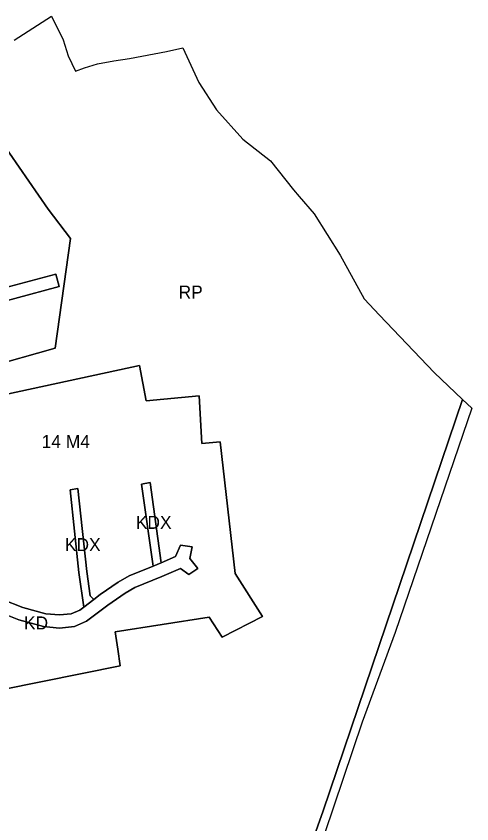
# Model space of a CAD drawing. Extents: x 7437831 to 7440315, y 5545798 to 5547888.
# Drawn here: x 7439964 to 7440315, y 5546851 to 5547473 of the extents above; entities that cross this region are included whole.
import ezdxf

# ---------------------------------------------------------------- set-up
doc = ezdxf.new("R2010")
doc.units = 0
doc.layers.add('linie_rozgraniczajace', color=7, linetype='Continuous')
doc.layers.add('oznaczenia_przeznaczen', color=7, linetype='Continuous')

msp = doc.modelspace()

# ---------------------------------------------------------------- linework, layer by layer
at = {"layer": 'linie_rozgraniczajace'}
for points in [[(7439963.01, 5547454.6), (7439991.67, 5547473.21), (7440000.6, 5547454.89), (7440004.46, 5547442.6), (7440010.06, 5547430.72), (7440017.22, 5547433.51), (7440027.12, 5547436.37), (7440039.57, 5547438.77), (7440051.74, 5547440.46), (7440080.33, 5547445.88), (7440092.89, 5547448.73), (7440105.07, 5547422.15), (7440118.61, 5547401.15), (7440138.87, 5547378.47), (7440160.22, 5547361.74), (7440178.05, 5547339.51), (7440182.37, 5547334.31), (7440194, 5547320.9), (7440214.02, 5547289.14), (7440232.3, 5547255.4), (7440244.18, 5547242.73), (7440286.26, 5547198.58), (7440308.05, 5547177.94), (7440200.75, 5546860.84), (7440127.28, 5546653.58)], [(7439941.63, 5547202.42), (7439994.44, 5547217.29), (7440006.23, 5547301.94), (7439989.21, 5547324.61), (7439951.69, 5547378.41)], [(7439951.69, 5547378.41), (7439989.21, 5547324.61), (7440006.23, 5547301.94), (7439994.44, 5547217.29), (7439941.63, 5547202.42)], [(7439929.04, 5547246.52), (7439997.61, 5547264.78), (7439995.02, 5547274.44), (7439925.61, 5547255.95)], [(7439925.61, 5547255.95), (7439995.02, 5547274.44), (7439997.61, 5547264.78), (7439929.04, 5547246.52)], [(7439892.92, 5546942.17), (7440044.56, 5546972.61), (7440042.79, 5546985.48), (7440040.74, 5546998.78), (7440113.06, 5547010.07), (7440123.08, 5546994.81), (7440154.06, 5547010.54), (7440133.02, 5547043.84), (7440121.64, 5547145.28), (7440107.55, 5547143.9), (7440105.31, 5547180.69), (7440064.52, 5547176.81), (7440059.38, 5547204.07), (7439948.78, 5547180.1)], [(7439948.78, 5547180.1), (7440059.38, 5547204.07), (7440064.52, 5547176.81), (7440105.31, 5547180.69), (7440107.55, 5547143.9), (7440121.64, 5547145.28), (7440133.02, 5547043.84), (7440154.06, 5547010.54), (7440123.08, 5546994.81), (7440113.06, 5547010.07), (7440040.74, 5546998.78), (7440042.79, 5546985.48), (7440044.56, 5546972.61), (7439892.92, 5546942.17)], [(7439936.88, 5547019.85), (7439966.48, 5547007.99), (7439985.57, 5547002.9), (7439997.86, 5547001.76), (7440009.46, 5547002.98), (7440018.66, 5547006.94), (7440035.1, 5547019.42), (7440048.31, 5547028.54), (7440055.98, 5547032.86), (7440076.73, 5547041.45), (7440091.03, 5547047.6), (7440097.55, 5547042.98), (7440104.36, 5547047.52), (7440098.28, 5547055.21), (7440099.9, 5547064.26), (7440090.96, 5547065.69), (7440087.08, 5547056.78), (7440076.17, 5547052.1), (7440067.66, 5547113.91), (7440060.9, 5547112.64), (7440069.89, 5547049.44), (7440051.59, 5547041.87), (7440043, 5547037.02), (7440029.23, 5547027.52), (7440024.35, 5547023.81), (7440021.4, 5547026.44), (7440018.79, 5547045.22), (7440012.09, 5547109.24), (7440006.18, 5547108.13), (7440012.84, 5547044.5), (7440016.52, 5547017.87), (7440013.59, 5547015.64), (7440006.91, 5547012.76), (7439997.8, 5547011.81), (7439987.33, 5547012.78), (7439969.62, 5547017.51), (7439953.87, 5547023.73)], [(7439953.87, 5547023.73), (7439969.62, 5547017.51), (7439987.33, 5547012.78), (7439997.8, 5547011.81), (7440006.91, 5547012.76), (7440013.59, 5547015.64), (7440016.52, 5547017.87), (7440024.35, 5547023.81), (7440029.23, 5547027.52), (7440043, 5547037.02), (7440051.59, 5547041.87), (7440069.89, 5547049.44), (7440076.17, 5547052.1), (7440087.08, 5547056.78), (7440090.96, 5547065.69), (7440099.9, 5547064.26), (7440098.28, 5547055.21), (7440104.36, 5547047.52), (7440097.55, 5547042.98), (7440091.03, 5547047.6), (7440076.73, 5547041.45), (7440055.98, 5547032.86), (7440048.31, 5547028.54), (7440035.1, 5547019.42), (7440018.66, 5547006.94), (7440009.46, 5547002.98), (7439997.86, 5547001.76), (7439985.57, 5547002.9), (7439966.48, 5547007.99), (7439936.88, 5547019.85)]]:
    msp.add_lwpolyline(points, dxfattribs=at)
for points in [[(7440308.05, 5547177.94), (7440315.29, 5547171.09), (7440256.26, 5546998.43), (7440230.77, 5546929.2), (7440194.34, 5546821.2), (7440137.83, 5546655.9), (7440115.26, 5546587.11), (7440104.3, 5546556.76), (7440101.52, 5546548.77), (7440096.01, 5546555.84), (7440127.28, 5546653.58), (7440200.75, 5546860.84)], [(7440067.66, 5547113.91), (7440076.17, 5547052.1), (7440069.89, 5547049.44), (7440060.9, 5547112.64)], [(7440012.09, 5547109.24), (7440018.79, 5547045.22), (7440021.4, 5547026.44), (7440024.35, 5547023.81), (7440016.52, 5547017.87), (7440012.84, 5547044.5), (7440006.18, 5547108.13)]]:
    msp.add_lwpolyline(points, close=True, dxfattribs=at)

# ---------------------------------------------------------------- texts
at = {"layer": 'oznaczenia_przeznaczen'}
for s, p in [('RP', (7440089.5432, 5547255.58)), ('14 M4', (7439984.1305, 5547140.48)), ('KDX', (7440056.6443, 5547078.15)), ('KDX', (7440002.0143, 5547061)), ('KD', (7439970.4927, 5547000.69))]:
    msp.add_text(s, height=10, dxfattribs=at).set_placement(p)

doc.saveas('drawing.dxf')
